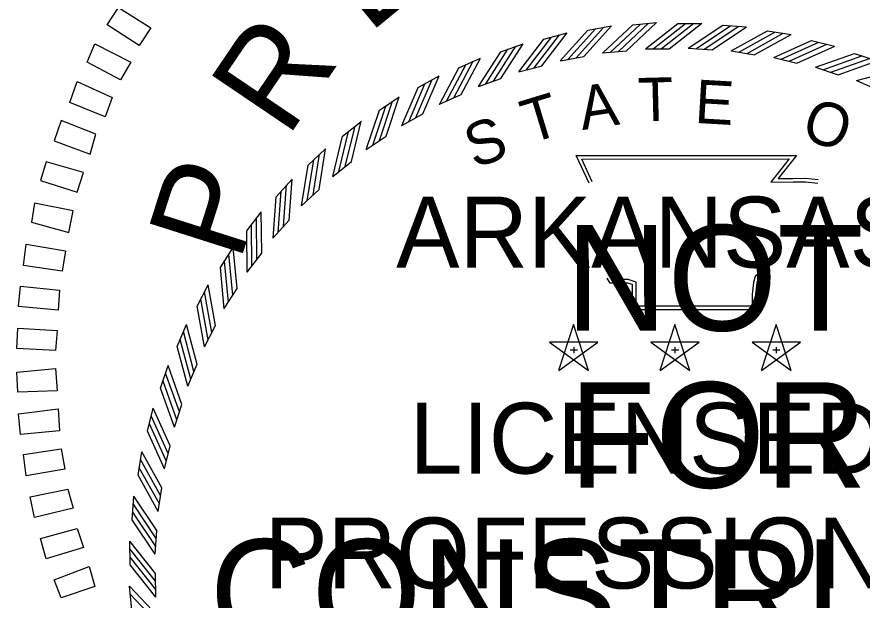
# Model space of a CAD drawing. Extents: x 16 to 1228743, y 11 to 152440.
# Drawn here: x 17.6615 to 17.7949, y 10.8959 to 10.988 of the extents above; entities that cross this region are included whole.
import ezdxf

# ---------------------------------------------------------------- set-up
doc = ezdxf.new("R2010")
doc.units = 0
doc.layers.add('STAMP_JUSTIN', color=7, linetype='Continuous')
doc.layers.add('STAMP_PRELIM', color=7, linetype='Continuous')

msp = doc.modelspace()

# ---------------------------------------------------------------- linework, layer by layer
at = {"layer": 'STAMP_JUSTIN'}
for p, q in [((17.75872, 10.98673), (17.76248, 10.98708)), ((17.76586, 10.98694), (17.76963, 10.98694)), ((17.75167, 10.98589), (17.75538, 10.98654)), ((17.77292, 10.98666), (17.77668, 10.98638)), ((17.77997, 10.98574), (17.7837, 10.98516)), ((17.74471, 10.98447), (17.74835, 10.98543)), ((17.78692, 10.98425), (17.79058, 10.98336)), ((17.73788, 10.98247), (17.74144, 10.98373)), ((17.76072, 10.98293), (17.7645, 10.98293)), ((17.7675, 10.98304), (17.77127, 10.98276)), ((17.7473, 10.98105), (17.75102, 10.9817)), ((17.75397, 10.98227), (17.75773, 10.98261)), ((17.77427, 10.98258), (17.778, 10.98199)), ((17.78097, 10.98157), (17.78464, 10.98068)), ((17.79372, 10.98219), (17.7973, 10.981)), ((17.73125, 10.97992), (17.73469, 10.98147)), ((17.74075, 10.97928), (17.74441, 10.98024)), ((17.78757, 10.98001), (17.79116, 10.97881)), ((17.72485, 10.97684), (17.72815, 10.97866)), ((17.73437, 10.97698), (17.73793, 10.97824)), ((17.79402, 10.97791), (17.79749, 10.97642)), ((17.71873, 10.97323), (17.72186, 10.97532)), ((17.7282, 10.97416), (17.73165, 10.97571)), ((17.72229, 10.97084), (17.7256, 10.97266)), ((17.71292, 10.96913), (17.71588, 10.97147)), ((17.71667, 10.96704), (17.71982, 10.96913)), ((17.70748, 10.96456), (17.71023, 10.96714)), ((17.71139, 10.96279), (17.71435, 10.96514)), ((17.70243, 10.95957), (17.70495, 10.96236)), ((17.70647, 10.95812), (17.70923, 10.9607)), ((17.69781, 10.95417), (17.70009, 10.95716)), ((17.70195, 10.95306), (17.70449, 10.95586)), ((17.69365, 10.9484), (17.69568, 10.95158)), ((17.69787, 10.94764), (17.70017, 10.95065)), ((17.68998, 10.94232), (17.69174, 10.94565)), ((17.69425, 10.94191), (17.69629, 10.94509)), ((17.68683, 10.93595), (17.68831, 10.93942)), ((17.69112, 10.93589), (17.69289, 10.93923)), ((17.74939, 10.93938), (17.74703, 10.93214)), ((17.75174, 10.93215), (17.74939, 10.93939)), ((17.76538, 10.93938), (17.76302, 10.93214)), ((17.76773, 10.93215), (17.76539, 10.93939)), ((17.78137, 10.93938), (17.77901, 10.93214)), ((17.78372, 10.93215), (17.78138, 10.93939)), ((17.75319, 10.93661), (17.74558, 10.93662)), ((17.74559, 10.93661), (17.75174, 10.93214)), ((17.74704, 10.93215), (17.7532, 10.93661)), ((17.76918, 10.93661), (17.76157, 10.93662)), ((17.76158, 10.93661), (17.76773, 10.93214)), ((17.76303, 10.93215), (17.76919, 10.93661)), ((17.78517, 10.93661), (17.77756, 10.93662)), ((17.77757, 10.93661), (17.78372, 10.93214)), ((17.77902, 10.93215), (17.78518, 10.93661)), ((17.74885, 10.9354), (17.74998, 10.9354)), ((17.7494, 10.93581), (17.7494, 10.93485)), ((17.76484, 10.9354), (17.76597, 10.9354)), ((17.76539, 10.93581), (17.76539, 10.93485)), ((17.78083, 10.9354), (17.78196, 10.9354)), ((17.78138, 10.93581), (17.78138, 10.93485)), ((17.68421, 10.92934), (17.6854, 10.93292)), ((17.68849, 10.92964), (17.68998, 10.93312)), ((17.68215, 10.92254), (17.68304, 10.9262)), ((17.68639, 10.92319), (17.68758, 10.92678)), ((17.68483, 10.91659), (17.68572, 10.92027)), ((17.68065, 10.91559), (17.68124, 10.91932)), ((17.68381, 10.90989), (17.6844, 10.91362)), ((17.67974, 10.90855), (17.68001, 10.91231)), ((17.68336, 10.90312), (17.68364, 10.90689)), ((17.67941, 10.90145), (17.67937, 10.90522)), ((17.68347, 10.89634), (17.68343, 10.90012)), ((17.67966, 10.89435), (17.67932, 10.8981))]:
    msp.add_line(p, q, dxfattribs=at)
for points in [[(17.75648, 10.98251), (17.76123, 10.98698)], [(17.75773, 10.98261), (17.76248, 10.98708)], [(17.76071, 10.98293), (17.76586, 10.98694)], [(17.76193, 10.98292), (17.76707, 10.98693)], [(17.76324, 10.98295), (17.76838, 10.98696)], [(17.76449, 10.98293), (17.76964, 10.98695)], [(17.74729, 10.98104), (17.75166, 10.98588)], [(17.74849, 10.98124), (17.75286, 10.98608)], [(17.74978, 10.9815), (17.75415, 10.98634)], [(17.75102, 10.9817), (17.75538, 10.98655)], [(17.75397, 10.98226), (17.75872, 10.98673)], [(17.75517, 10.98236), (17.75993, 10.98683)], [(17.76749, 10.98303), (17.77292, 10.98666)], [(17.7687, 10.98293), (17.77413, 10.98656)], [(17.77001, 10.98287), (17.77544, 10.98649)], [(17.77126, 10.98276), (17.77669, 10.98639)], [(17.77426, 10.98258), (17.77997, 10.98574)], [(17.77546, 10.98238), (17.78116, 10.98554)], [(17.74075, 10.97927), (17.7447, 10.98446)], [(17.74192, 10.97957), (17.74588, 10.98476)], [(17.74318, 10.97993), (17.74714, 10.98512)], [(17.7444, 10.98024), (17.74835, 10.98543)], [(17.77676, 10.9822), (17.78246, 10.98537)], [(17.778, 10.982), (17.7837, 10.98516)], [(17.78097, 10.98157), (17.78691, 10.98425)], [(17.73552, 10.97737), (17.73903, 10.98286)], [(17.73674, 10.97783), (17.74025, 10.98333)], [(17.73793, 10.97824), (17.74144, 10.98373)], [(17.78214, 10.98127), (17.78809, 10.98395)], [(17.78342, 10.98099), (17.78937, 10.98367)], [(17.78464, 10.98068), (17.79059, 10.98336)], [(17.73437, 10.97697), (17.73788, 10.98247)], [(17.78757, 10.98001), (17.79371, 10.98219)], [(17.78871, 10.97961), (17.79486, 10.98179)], [(17.72931, 10.97464), (17.73236, 10.98041)], [(17.7305, 10.9752), (17.73354, 10.98097)], [(17.73165, 10.97571), (17.73469, 10.98147)], [(17.78997, 10.97923), (17.79611, 10.98141)], [(17.79115, 10.97882), (17.7973, 10.981)], [(17.7282, 10.97415), (17.73125, 10.97992)], [(17.79401, 10.9779), (17.80032, 10.97957)], [(17.72449, 10.97207), (17.72705, 10.97807)], [(17.72559, 10.97266), (17.72815, 10.97866)], [(17.72229, 10.97083), (17.72485, 10.97683)], [(17.72336, 10.97141), (17.72592, 10.97741)], [(17.71981, 10.96913), (17.72187, 10.97532)], [(17.71769, 10.9677), (17.71974, 10.97389)], [(17.71876, 10.96845), (17.72081, 10.97464)], [(17.71667, 10.96703), (17.71873, 10.97322)], [(17.71434, 10.96514), (17.71588, 10.97148)], [(17.71234, 10.96353), (17.71388, 10.96987)], [(17.71335, 10.96437), (17.71489, 10.97071)], [(17.71138, 10.96278), (17.71292, 10.96912)], [(17.70922, 10.9607), (17.71023, 10.96715)], [(17.7083, 10.95985), (17.7093, 10.9663)], [(17.75182, 10.96171), (17.74981, 10.96606), (17.78458, 10.96608), (17.78167, 10.96243), (17.78403, 10.96246), (17.78601, 10.96249), (17.78798, 10.96227)], [(17.75232, 10.96194), (17.75067, 10.96551), (17.78343, 10.96553), (17.78052, 10.96187), (17.78404, 10.96191), (17.78598, 10.96194), (17.78792, 10.96173)], [(17.70647, 10.95811), (17.70748, 10.96456)], [(17.70736, 10.95894), (17.70837, 10.96538)], [(17.70448, 10.95586), (17.70495, 10.96237)], [(17.70278, 10.95395), (17.70325, 10.96045)], [(17.70363, 10.95494), (17.7041, 10.96144)], [(17.70195, 10.95305), (17.70243, 10.95956)], [(17.70016, 10.95064), (17.70009, 10.95717)], [(17.69862, 10.94859), (17.69855, 10.95512)], [(17.69939, 10.94965), (17.69932, 10.95618)], [(17.69787, 10.94764), (17.69781, 10.95416)], [(17.69628, 10.94509), (17.69568, 10.95158)], [(17.6956, 10.94404), (17.69499, 10.95053)], [(17.69425, 10.9419), (17.69365, 10.9484)], [(17.69492, 10.94292), (17.69431, 10.94941)], [(17.7791, 10.94714), (17.77851, 10.94666), (17.77831, 10.94594), (17.77811, 10.94413), (17.77811, 10.94173), (17.7587, 10.94173), (17.7587, 10.94498), (17.7587, 10.9457), (17.75792, 10.94594), (17.75515, 10.94594), (17.75466, 10.94669)], [(17.77875, 10.94757), (17.77802, 10.94697), (17.77777, 10.94604), (17.77756, 10.94416), (17.77756, 10.94228), (17.75925, 10.94228), (17.75925, 10.94498), (17.75925, 10.9461), (17.758, 10.94649), (17.75545, 10.94649), (17.75512, 10.94699)], [(17.69288, 10.93923), (17.69174, 10.94565)], [(17.69228, 10.93813), (17.69114, 10.94455)], [(17.6917, 10.93696), (17.69056, 10.94338)], [(17.69112, 10.93589), (17.68998, 10.94231)], [(17.68997, 10.93311), (17.68831, 10.93942)], [(17.68947, 10.93196), (17.6878, 10.93827)], [(17.68898, 10.93075), (17.68731, 10.93705)], [(17.68849, 10.92964), (17.68683, 10.93594)], [(17.68758, 10.92678), (17.6854, 10.93292)], [(17.68717, 10.92559), (17.68499, 10.93174)], [(17.68678, 10.92434), (17.6846, 10.93048)], [(17.68639, 10.92319), (17.68421, 10.92934)], [(17.68572, 10.92026), (17.68304, 10.92621)], [(17.68541, 10.91904), (17.68273, 10.92499)], [(17.68513, 10.91777), (17.68245, 10.92371)], [(17.68483, 10.91659), (17.68215, 10.92254)], [(17.6844, 10.91362), (17.68124, 10.91932)], [(17.68419, 10.91238), (17.68103, 10.91808)], [(17.68402, 10.91108), (17.68085, 10.91679)], [(17.68382, 10.90988), (17.68065, 10.91559)], [(17.68363, 10.90689), (17.68001, 10.91231)], [(17.68353, 10.90563), (17.67991, 10.91106)], [(17.68346, 10.90433), (17.67984, 10.90975)], [(17.68336, 10.90312), (17.67974, 10.90854)], [(17.68343, 10.90011), (17.67937, 10.90522)], [(17.68343, 10.89886), (17.67937, 10.90397)], [(17.68347, 10.89755), (17.67941, 10.90266)], [(17.68347, 10.89634), (17.67941, 10.90144)], [(17.68378, 10.89335), (17.67932, 10.8981)], [(17.68389, 10.8921), (17.67942, 10.89685)]]:
    msp.add_lwpolyline(points, dxfattribs=at)
at = {"layer": 'STAMP_PRELIM'}
for p, q in [((17.67577, 10.98673), (17.67756, 10.98942)), ((17.67756, 10.98942), (17.68269, 10.98624)), ((17.68081, 10.98347), (17.67577, 10.98673)), ((17.68269, 10.98624), (17.68081, 10.98347)), ((17.6726, 10.98079), (17.67382, 10.98372)), ((17.67382, 10.98372), (17.67951, 10.98079)), ((17.67788, 10.97802), (17.6726, 10.98079)), ((17.67951, 10.98079), (17.67788, 10.97802)), ((17.66991, 10.97444), (17.67105, 10.97777)), ((17.67105, 10.97777), (17.67658, 10.97526)), ((17.67658, 10.97526), (17.67544, 10.97217)), ((17.67544, 10.97217), (17.66991, 10.97444)), ((17.66853, 10.97159), (17.66739, 10.96842)), ((17.67398, 10.96947), (17.66853, 10.97159)), ((17.66739, 10.96842), (17.67309, 10.96631)), ((17.67309, 10.96631), (17.67398, 10.96947)), ((17.66617, 10.96508), (17.66528, 10.96215)), ((17.67203, 10.96338), (17.66617, 10.96508)), ((17.67105, 10.96028), (17.67203, 10.96338)), ((17.66528, 10.96215), (17.67105, 10.96028)), ((17.6643, 10.95857), (17.66381, 10.95556)), ((17.6704, 10.95735), (17.6643, 10.95857)), ((17.66975, 10.95394), (17.6704, 10.95735)), ((17.66381, 10.95556), (17.66975, 10.95394)), ((17.66259, 10.94873), (17.663, 10.95206)), ((17.663, 10.95206), (17.66918, 10.95101)), ((17.66918, 10.95101), (17.66869, 10.94783)), ((17.66869, 10.94783), (17.66259, 10.94873)), ((17.66177, 10.94222), (17.6621, 10.94547)), ((17.6621, 10.94547), (17.66828, 10.94482)), ((17.66828, 10.94482), (17.66804, 10.94164)), ((17.66804, 10.94164), (17.66177, 10.94222)), ((17.66153, 10.93562), (17.6617, 10.9388)), ((17.6617, 10.9388), (17.66788, 10.93847)), ((17.66788, 10.93847), (17.66763, 10.93529)), ((17.66763, 10.93529), (17.66153, 10.93562)), ((17.66153, 10.93188), (17.66763, 10.93245)), ((17.66763, 10.93245), (17.66788, 10.92895)), ((17.6617, 10.92871), (17.66153, 10.93188)), ((17.66788, 10.92895), (17.6617, 10.92871)), ((17.66177, 10.92529), (17.66804, 10.9261)), ((17.66804, 10.9261), (17.66828, 10.9226)), ((17.6621, 10.92204), (17.66177, 10.92529)), ((17.66828, 10.9226), (17.6621, 10.92204)), ((17.66259, 10.91886), (17.66853, 10.91976)), ((17.663, 10.91552), (17.66259, 10.91886)), ((17.66853, 10.91976), (17.6691, 10.91658)), ((17.6691, 10.91658), (17.663, 10.91552)), ((17.66365, 10.91218), (17.66958, 10.91341)), ((17.6643, 10.90893), (17.66365, 10.91218)), ((17.66958, 10.91341), (17.6704, 10.91039)), ((17.6704, 10.91039), (17.6643, 10.90893)), ((17.66528, 10.9056), (17.67105, 10.90722)), ((17.67105, 10.90722), (17.67203, 10.90421)), ((17.66617, 10.90242), (17.66528, 10.9056)), ((17.67203, 10.90421), (17.66617, 10.90242)), ((17.66739, 10.89909), (17.67293, 10.9012)), ((17.67293, 10.9012), (17.67382, 10.89802)), ((17.66853, 10.89623), (17.66739, 10.89909)), ((17.67382, 10.89802), (17.66853, 10.89623))]:
    msp.add_line(p, q, dxfattribs=at)

# ---------------------------------------------------------------- texts
at = {"layer": 'STAMP_JUSTIN'}
for s, rotation, p in [('T', 1.4789, (17.75961, 10.97145)), ('E', 356.672, (17.76839, 10.97124)), ('A', 8.6788, (17.75076, 10.97008)), ('T', 16.9015, (17.74243, 10.96791)), ('O', 341.2218, (17.78504, 10.96889)), ('S', 19.7726, (17.73371, 10.96399))]:
    msp.add_text(s, height=0.00686, rotation=rotation, dxfattribs=at).set_placement(p)
for s, height, p in [('ARKANSAS', 0.011194, (17.72139, 10.94839)), ('LICENSED', 0.011194, (17.72352, 10.91586)), ('PROFESSIONAL', 0.0111936, (17.7006, 10.89773))]:
    msp.add_text(s, height=height, dxfattribs=at).set_placement(p)
at = {"layer": 'STAMP_PRELIM'}
for s, rotation, p in [('E', 39.5095, (17.71703, 10.98519)), ('R', 55.9266, (17.70418, 10.96866)), ('P', 72.3438, (17.69669, 10.94905))]:
    msp.add_text(s, height=0.01542, rotation=rotation, dxfattribs=at).set_placement(p)
for s, height, p in [('NOT', 0.016659, (17.74812, 10.93843)), ('FOR', 0.016659, (17.74867, 10.91363)), ('CONSTRUCTION', 0.0166586, (17.69196, 10.88883))]:
    msp.add_text(s, height=height, dxfattribs=at).set_placement(p)

doc.saveas('drawing.dxf')
